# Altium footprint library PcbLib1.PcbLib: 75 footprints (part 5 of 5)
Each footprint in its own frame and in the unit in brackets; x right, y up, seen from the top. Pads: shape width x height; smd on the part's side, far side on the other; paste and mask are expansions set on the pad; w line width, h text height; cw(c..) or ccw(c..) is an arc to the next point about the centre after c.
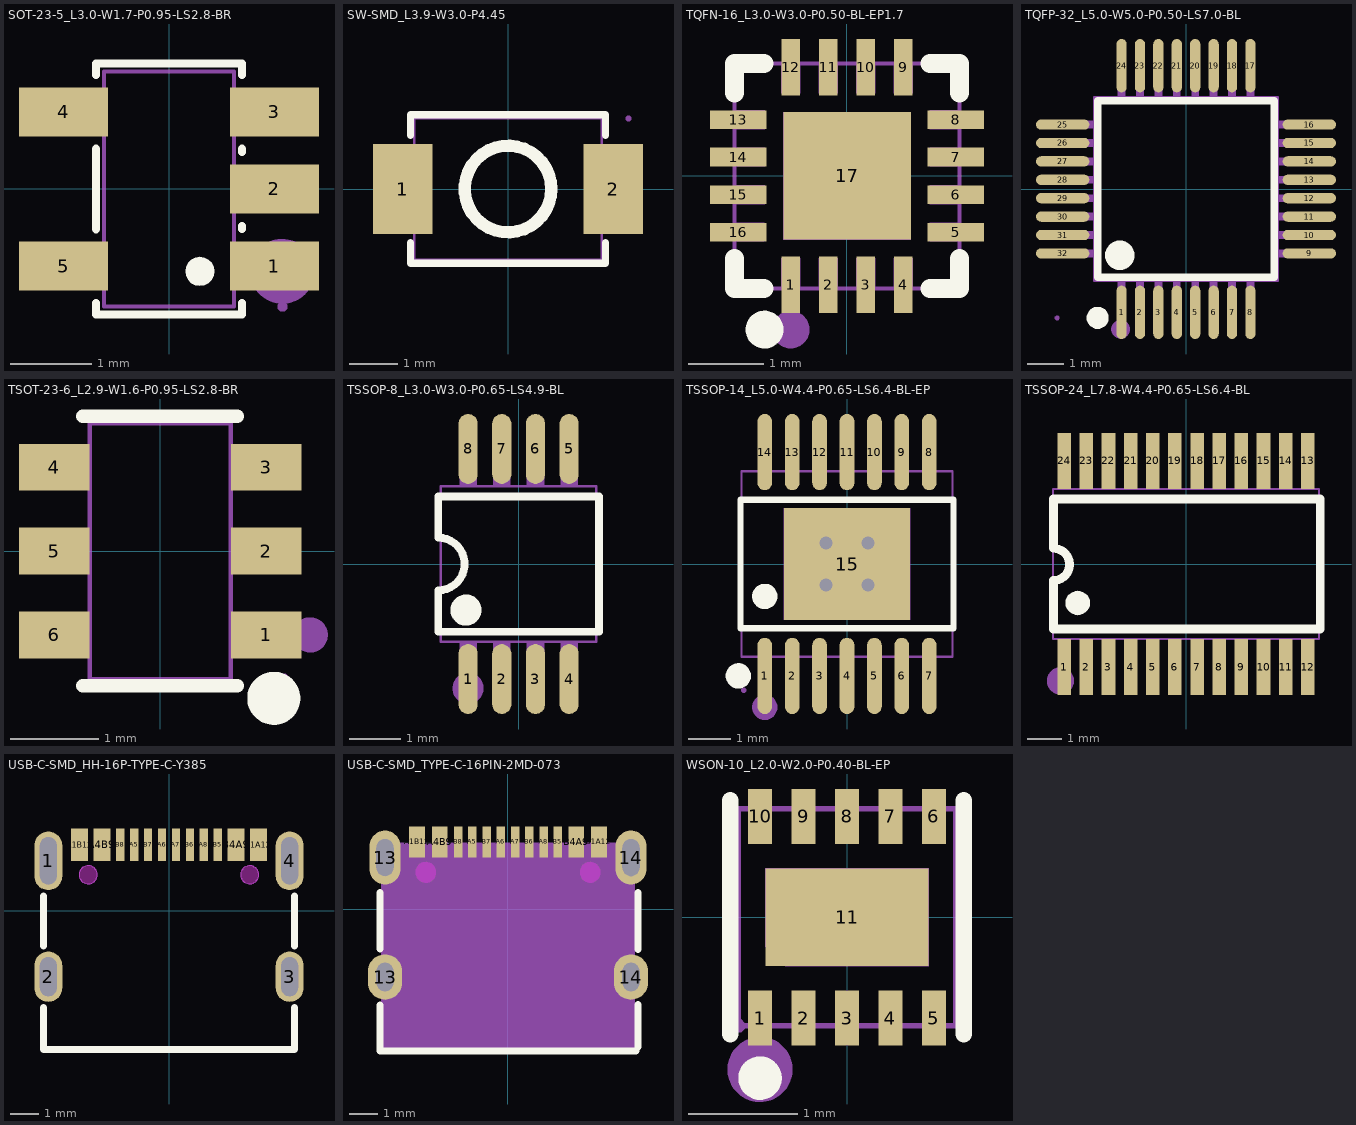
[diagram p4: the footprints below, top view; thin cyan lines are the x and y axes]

## SOT-23-5_L3.0-W1.7-P0.95-LS2.8-BR [mm]
pads (5):
  rect 1.1x0.6 smd: 1(1.3,-0.95) 2(1.3,0) 3(1.3,0.95) 4(-1.3,0.95) 5(-1.3,-0.95)
Top Overlay:
  region: 0.204,-1.016 0.212,-0.961 0.237,-0.911 0.276,-0.871 0.326,-0.846 0.381,-0.837 0.436,-0.846 0.486,-0.871 0.525,-0.911 0.55,-0.961 0.558,-1.016 0.55,-1.071 0.525,-1.121 0.486,-1.161 0.436,-1.186 0.381,-1.195 0.326,-1.186 0.276,-1.161 0.237,-1.121 0.212,-1.071 0.204,-1.016
  lines w0.1: -0.9,-1.404 -0.9,-1.55 0.9,-1.55 0.9,-1.404 ; -0.9,-0.496 -0.9,0.496 ; -0.9,1.404 -0.9,1.55 0.9,1.55 0.9,1.404 ; 0.9,-0.496 0.9,-0.454 ; 0.9,0.454 0.9,0.496
Mechanical 2:
  circle w0.4: c1.397,-1.016 r0.2
Mechanical 6:
  lines w0.051: -0.8,-1.45 -0.8,1.45 0.8,1.45 0.8,-1.45 -0.8,-1.45
Mechanical 7:
  region: -0.96,-1.15 -0.96,-0.75 -0.79,-0.75 -0.79,-1.15
  region: -0.96,0.75 -0.96,1.15 -0.79,1.15 -0.79,0.75
  region: 0.79,0.75 0.79,1.15 0.96,1.15 0.96,0.75
  region: 0.79,-0.2 0.79,0.2 0.96,0.2 0.96,-0.2
  region: 0.79,-1.15 0.79,-0.75 0.96,-0.75 0.96,-1.15
Mechanical 8:
  region: 1.46,-1.45 1.46,-1.475 1.425,-1.51 1.375,-1.51 1.34,-1.475 1.34,-1.45 1.34,-1.425 1.375,-1.39 1.425,-1.39 1.46,-1.425 1.46,-1.45
Mechanical 9:
  region: -1.4,-1.15 -1.4,-0.75 -0.95,-0.75 -0.95,-1.15
  region: -1.4,0.75 -1.4,1.15 -0.95,1.15 -0.95,0.75
  region: 0.95,0.75 0.95,1.15 1.4,1.15 1.4,0.75
  region: 0.95,-0.2 0.95,0.2 1.4,0.2 1.4,-0.2
  region: 0.95,-1.15 0.95,-0.75 1.4,-0.75 1.4,-1.15

## SW-SMD_L3.9-W3.0-P4.45 [mm]
pads (2):
  rect 1.23x1.86 smd: 1(-2.185,0) 2(2.185,0)
Top Overlay:
  circle w0.254: c0,0 r0.9
  lines w0.152: -2.026,-1.11 -2.026,-1.541 2.026,-1.541 2.026,-1.11 ; -2.026,1.11 -2.026,1.541 2.026,1.541 2.026,1.11
Mechanical 6:
  lines w0.051: -1.95,-1.465 -1.95,1.465 1.95,1.465 1.95,-1.465 -1.95,-1.465
Mechanical 8:
  region: 2.56,1.465 2.56,1.44 2.525,1.405 2.475,1.405 2.44,1.44 2.44,1.465 2.44,1.49 2.475,1.525 2.525,1.525 2.56,1.49 2.56,1.465
Mechanical 9:
  region: -2.5,0.65 -2.5,-0.65 -1.6,-0.65 -1.6,0.65
  region: 2.5,0.65 2.5,-0.65 1.6,-0.65 1.6,0.65

## TQFN-16_L3.0-W3.0-P0.50-BL-EP1.7 [mm]
pads (17):
  rect 0.25x0.75 smd paste-100 mask+0.051: 1(-0.748,-1.45) 2(-0.249,-1.45) 3(0.252,-1.45) 4(0.751,-1.45) 9(0.75,1.45) 10(0.25,1.45) 11(-0.25,1.45) 12(-0.749,1.45)
  rect 0.75x0.25 smd paste-100 mask+0.051: 5(1.45,-0.75) 6(1.45,-0.25) 7(1.45,0.25) 8(1.45,0.75) 13(-1.45,0.75) 14(-1.45,0.25) 15(-1.45,-0.25) 16(-1.45,-0.75)
  rect 1.7x1.7 smd paste-100 mask+0.051: 17(0,0)
Top Overlay:
  circle w0.254: c-1.1,-2.05 r0.125
  lines w0.254: -1.5,-1.104 -1.5,-1.5 -1.105,-1.5 ; -1.5,1.108 -1.5,1.5 -1.105,1.5 ; 1.106,1.5 1.5,1.5 1.5,1.108 ; 1.108,-1.5 1.5,-1.5 1.5,-1.104
Top Paste:
  region: 0.876,-1.075 0.626,-1.075 0.626,-1.825 0.876,-1.825
  region: 0.377,-1.075 0.127,-1.075 0.127,-1.825 0.377,-1.825
  region: -0.124,-1.075 -0.374,-1.075 -0.374,-1.825 -0.124,-1.825
  region: -0.623,-1.075 -0.873,-1.075 -0.873,-1.825 -0.623,-1.825
  region: 0.876,1.825 0.626,1.825 0.626,1.075 0.876,1.075
  region: 0.376,1.825 0.126,1.825 0.126,1.075 0.376,1.075
  region: -0.124,1.825 -0.374,1.825 -0.374,1.075 -0.124,1.075
  region: -0.624,1.825 -0.874,1.825 -0.874,1.075 -0.624,1.075
  region: 1.825,-0.875 1.825,-0.625 1.075,-0.625 1.075,-0.875
  region: 1.825,-0.375 1.825,-0.125 1.075,-0.125 1.075,-0.375
  region: 1.825,0.125 1.825,0.375 1.075,0.375 1.075,0.125
  region: 1.825,0.625 1.825,0.875 1.075,0.875 1.075,0.625
  region: -1.075,-0.875 -1.075,-0.625 -1.825,-0.625 -1.825,-0.875
  region: -1.075,-0.375 -1.075,-0.125 -1.825,-0.125 -1.825,-0.375
  region: -1.075,0.125 -1.075,0.375 -1.825,0.375 -1.825,0.125
  region: -1.075,0.625 -1.075,0.875 -1.825,0.875 -1.825,0.625
  region: -0.68,0.68 0.68,0.68 0.68,-0.68 -0.68,-0.68
Mechanical 2:
  circle w0.25: c-0.75,-2.05 r0.125
Mechanical 6:
  lines w0.051: -1.5,-1.5 -1.5,1.5 1.5,1.5 1.5,-1.5 -1.5,-1.5
Mechanical 8:
  region: -1.44,-1.5 -1.44,-1.525 -1.475,-1.56 -1.525,-1.56 -1.56,-1.525 -1.56,-1.5 -1.56,-1.475 -1.525,-1.44 -1.475,-1.44 -1.44,-1.475 -1.44,-1.5
Mechanical 9:
  region: -0.85,0.85 0.85,0.85 0.85,-0.85 -0.85,-0.85
  region: -0.623,-1.5 -0.873,-1.5 -0.873,-1.1 -0.623,-1.1
  region: -0.124,-1.5 -0.374,-1.5 -0.374,-1.1 -0.124,-1.1
  region: 0.377,-1.5 0.127,-1.5 0.127,-1.1 0.377,-1.1
  region: 0.876,-1.5 0.626,-1.5 0.626,-1.1 0.876,-1.1
  region: 1.1,-0.875 1.1,-0.625 1.5,-0.625 1.5,-0.875
  region: 1.1,-0.375 1.1,-0.125 1.5,-0.125 1.5,-0.375
  region: 1.1,0.125 1.1,0.375 1.5,0.375 1.5,0.125
  region: 1.1,0.625 1.1,0.875 1.5,0.875 1.5,0.625
  region: 0.625,1.5 0.875,1.5 0.875,1.1 0.625,1.1
  region: 0.125,1.5 0.375,1.5 0.375,1.1 0.125,1.1
  region: -0.374,1.5 -0.124,1.5 -0.124,1.1 -0.374,1.1
  region: -0.874,1.5 -0.624,1.5 -0.624,1.1 -0.874,1.1
  region: -1.1,0.875 -1.1,0.625 -1.5,0.625 -1.5,0.875
  region: -1.1,0.375 -1.1,0.125 -1.5,0.125 -1.5,0.375
  region: -1.1,-0.125 -1.1,-0.375 -1.5,-0.375 -1.5,-0.125
  region: -1.1,-0.625 -1.1,-0.875 -1.5,-0.875 -1.5,-0.625

## TQFP-32_L5.0-W5.0-P0.50-LS7.0-BL [mm]
pads (32):
  oval 0.28x1.45 smd: 1(-1.75,-3.35) 2(-1.25,-3.35) 3(-0.75,-3.35) 4(-0.25,-3.35) 5(0.25,-3.35) 6(0.75,-3.35) 7(1.25,-3.35) 8(1.75,-3.35) 17(1.75,3.35) 18(1.25,3.35) 19(0.75,3.35) 20(0.25,3.35) 21(-0.25,3.35) 22(-0.75,3.35) 23(-1.25,3.35) 24(-1.75,3.35)
  oval 1.45x0.28 smd: 9(3.35,-1.75) 10(3.35,-1.25) 11(3.35,-0.75) 12(3.35,-0.25) 13(3.35,0.25) 14(3.35,0.75) 15(3.35,1.25) 16(3.35,1.75) 25(-3.35,1.75) 26(-3.35,1.25) 27(-3.35,0.75) 28(-3.35,0.25) 29(-3.35,-0.25) 30(-3.35,-0.75) 31(-3.35,-1.25) 32(-3.35,-1.75)
Top Overlay:
  lines w0.2: -2.4,-2.4 -2.4,2.4 2.4,2.4 2.4,-2.4 -2.4,-2.4
  lines w0.3: -2.4,-3.35 ccw(c-2.399,-3.5) -2.398,-3.35
  lines w0.4: -1.801,-1.6 ccw(c-1.798,-1.8) -1.796,-1.6
Mechanical 2:
  circle w0.254: c-1.778,-3.81 r0.127
Mechanical 6:
  lines w0.051: -2.5,-2.5 -2.5,2.5 2.5,2.5 2.5,-2.5 -2.5,-2.5
Mechanical 7:
  drawing of 32 lines, arcs and shapes, not listed
Mechanical 8:
  region: -3.44,-3.5 -3.44,-3.525 -3.475,-3.56 -3.525,-3.56 -3.56,-3.525 -3.56,-3.5 -3.56,-3.475 -3.525,-3.44 -3.475,-3.44 -3.44,-3.475 -3.44,-3.5
Mechanical 9:
  drawing of 32 lines, arcs and shapes, not listed

## TSOT-23-6_L2.9-W1.6-P0.95-LS2.8-BR [mm]
pads (6):
  rect 0.8x0.532 smd: 1(1.2,-0.95) 2(1.2,0) 3(1.2,0.95) 4(-1.2,0.95) 5(-1.2,0) 6(-1.2,-0.95)
Top Overlay:
  circle w0.3: c1.287,-1.669 r0.15
  lines w0.152: -0.876,-1.526 0.876,-1.526 ; -0.876,1.526 0.876,1.526
Mechanical 2:
  circle w0.2: c1.7,-0.95 r0.1
Mechanical 6:
  lines w0.051: -0.8,-1.45 0.8,-1.45 0.8,1.45 -0.8,1.45 -0.8,-1.45
Mechanical 7:
  region: -0.96,-1.15 -0.96,-0.75 -0.79,-0.75 -0.79,-1.15
  region: -0.96,-0.2 -0.96,0.2 -0.79,0.2 -0.79,-0.2
  region: -0.96,0.75 -0.96,1.15 -0.79,1.15 -0.79,0.75
  region: 0.79,0.75 0.79,1.15 0.96,1.15 0.96,0.75
  region: 0.79,-0.2 0.79,0.2 0.96,0.2 0.96,-0.2
  region: 0.79,-1.15 0.79,-0.75 0.96,-0.75 0.96,-1.15
Mechanical 8:
  region: 1.46,-1.45 1.46,-1.475 1.425,-1.51 1.375,-1.51 1.34,-1.475 1.34,-1.45 1.34,-1.425 1.375,-1.39 1.425,-1.39 1.46,-1.425 1.46,-1.45
Mechanical 9:
  region: -0.95,-1.15 -0.95,-0.75 -1.4,-0.75 -1.4,-1.15
  region: -0.95,-0.2 -0.95,0.2 -1.4,0.2 -1.4,-0.2
  region: -0.95,0.75 -0.95,1.15 -1.4,1.15 -1.4,0.75
  region: 0.95,0.75 0.95,1.15 1.4,1.15 1.4,0.75
  region: 0.95,-0.2 0.95,0.2 1.4,0.2 1.4,-0.2
  region: 0.95,-1.15 0.95,-0.75 1.4,-0.75 1.4,-1.15

## TSSOP-8_L3.0-W3.0-P0.65-LS4.9-BL [mm]
pads (8):
  oval 0.37x1.35 smd: 1(-0.975,-2.22) 2(-0.325,-2.22) 3(0.325,-2.22) 4(0.975,-2.22) 5(0.975,2.22) 6(0.325,2.22) 7(-0.325,2.22) 8(-0.975,2.22)
Top Overlay:
  circle w0.3: c-1.016,-0.889 r0.15
  lines w0.152: 1.552,1.298 1.552,-1.308 -1.552,-1.308 -1.552,-0.508 ccw(c-1.552,0) -1.552,0.508 -1.552,1.302 1.552,1.302
Mechanical 2:
  circle w0.3: c-0.975,-2.4 r0.15
Mechanical 6:
  lines w0.051: -1.5,-1.5 -1.5,1.5 1.5,1.5 1.5,-1.5 -1.5,-1.5
Mechanical 7:
  region: 0.16,1.49 0.16,1.91 0.49,1.91 0.49,1.49
  region: -0.49,1.49 -0.49,1.91 -0.16,1.91 -0.16,1.49
  region: -1.14,1.49 -1.14,1.91 -0.81,1.91 -0.81,1.49
  region: 0.16,-1.91 0.16,-1.49 0.49,-1.49 0.49,-1.91
  region: -0.49,-1.91 -0.49,-1.49 -0.16,-1.49 -0.16,-1.91
  region: -1.14,-1.91 -1.14,-1.49 -0.81,-1.49 -0.81,-1.91
  region: 0.81,1.49 0.81,1.91 1.14,1.91 1.14,1.49
  region: 0.81,-1.91 0.81,-1.49 1.14,-1.49 1.14,-1.91
Mechanical 8:
  region: -0.956,-0.889 -0.956,-0.914 -0.991,-0.949 -1.041,-0.949 -1.076,-0.914 -1.076,-0.889 -1.076,-0.864 -1.041,-0.829 -0.991,-0.829 -0.956,-0.864 -0.956,-0.889
Mechanical 9:
  region: 0.16,1.9 0.16,2.45 0.49,2.45 0.49,1.9
  region: -0.49,1.9 -0.49,2.45 -0.16,2.45 -0.16,1.9
  region: -1.14,1.9 -1.14,2.45 -0.81,2.45 -0.81,1.9
  region: 0.16,-2.45 0.16,-1.9 0.49,-1.9 0.49,-2.45
  region: -0.49,-2.45 -0.49,-1.9 -0.16,-1.9 -0.16,-2.45
  region: -1.14,-2.45 -1.14,-1.9 -0.81,-1.9 -0.81,-2.45
  region: 0.81,1.9 0.81,2.45 1.14,2.45 1.14,1.9
  region: 0.81,-2.45 0.81,-1.9 1.14,-1.9 1.14,-2.45

## TSSOP-14_L5.0-W4.4-P0.65-LS6.4-BL-EP [mm]
pads (15):
  oval 0.35x1.809 smd: 1(-1.95,-2.655) 2(-1.3,-2.655) 3(-0.65,-2.655) 4(0,-2.655) 5(0.65,-2.655) 6(1.3,-2.655) 7(1.95,-2.655) 8(1.95,2.655) 9(1.3,2.655) 10(0.65,2.655) 11(0,2.655) 12(-0.65,2.655) 13(-1.3,2.655) 14(-1.95,2.655)
  rect 3x2.65 smd: 15(0,0)
via 0.495,-0.495 diameter 0.61 hole 0.305
via -0.495,-0.495 diameter 0.61 hole 0.305
via -0.495,0.495 diameter 0.61 hole 0.305
via 0.495,0.495 diameter 0.61 hole 0.305
Top Overlay:
  circle w0.3: c-2.577,-2.655 r0.15
  circle w0.3: c-1.95,-0.769 r0.15
  lines w0.152: -2.526,-1.521 2.526,-1.521 2.526,1.521 -2.526,1.521 -2.526,-1.521
Mechanical 2:
  circle w0.3: c-1.95,-3.4 r0.15
Mechanical 6:
  lines w0.051: -2.5,-2.2 2.5,-2.2 2.5,2.2 -2.5,2.2 -2.5,-2.2
Mechanical 7:
  region: 1.825,2.37 1.825,1.94 2.075,1.94 2.075,2.37
  region: 1.175,2.37 1.175,1.94 1.425,1.94 1.425,2.37
  region: 0.525,2.37 0.525,1.94 0.775,1.94 0.775,2.37
  region: -0.125,2.37 -0.125,1.94 0.125,1.94 0.125,2.37
  region: -0.775,2.37 -0.775,1.94 -0.525,1.94 -0.525,2.37
  region: -1.425,2.37 -1.425,1.94 -1.175,1.94 -1.175,2.37
  region: -2.075,2.37 -2.075,1.94 -1.825,1.94 -1.825,2.37
  region: 1.825,-2.37 1.825,-1.94 2.075,-1.94 2.075,-2.37
  region: 1.175,-2.37 1.175,-1.94 1.425,-1.94 1.425,-2.37
  region: 0.525,-2.37 0.525,-1.94 0.775,-1.94 0.775,-2.37
  region: -0.125,-2.37 -0.125,-1.94 0.125,-1.94 0.125,-2.37
  region: -0.775,-2.37 -0.775,-1.94 -0.525,-1.94 -0.525,-2.37
  region: -1.425,-2.37 -1.425,-1.94 -1.175,-1.94 -1.175,-2.37
  region: -2.075,-2.37 -2.075,-1.94 -1.825,-1.94 -1.825,-2.37
Mechanical 8:
  region: -2.39,-3 -2.39,-3.025 -2.425,-3.06 -2.475,-3.06 -2.51,-3.025 -2.51,-3 -2.51,-2.975 -2.475,-2.94 -2.425,-2.94 -2.39,-2.975 -2.39,-3
Mechanical 9:
  region: -1.5,-1.325 -1.5,1.325 1.5,1.325 1.5,-1.325
  region: 1.825,3 1.825,2.36 2.075,2.36 2.075,3
  region: 1.175,3 1.175,2.36 1.425,2.36 1.425,3
  region: 0.525,3 0.525,2.36 0.775,2.36 0.775,3
  region: -0.125,3 -0.125,2.36 0.125,2.36 0.125,3
  region: -0.775,3 -0.775,2.36 -0.525,2.36 -0.525,3
  region: -1.425,3 -1.425,2.36 -1.175,2.36 -1.175,3
  region: -2.075,3 -2.075,2.36 -1.825,2.36 -1.825,3
  region: 1.825,-3 1.825,-2.36 2.075,-2.36 2.075,-3
  region: 1.175,-3 1.175,-2.36 1.425,-2.36 1.425,-3
  region: 0.525,-3 0.525,-2.36 0.775,-2.36 0.775,-3
  region: -0.125,-3 -0.125,-2.36 0.125,-2.36 0.125,-3
  region: -0.775,-3 -0.775,-2.36 -0.525,-2.36 -0.525,-3
  region: -1.425,-3 -1.425,-2.36 -1.175,-2.36 -1.175,-3
  region: -2.075,-3 -2.075,-2.36 -1.825,-2.36 -1.825,-3

## TSSOP-24_L7.8-W4.4-P0.65-LS6.4-BL [mm]
pads (24):
  rect 0.4x1.65 smd: 1(-3.575,-3.023) 2(-2.925,-3.023) 3(-2.275,-3.023) 4(-1.625,-3.023) 5(-0.975,-3.023) 6(-0.325,-3.023) 7(0.325,-3.023) 8(0.975,-3.023) 9(1.625,-3.023) 10(2.275,-3.023) 11(2.925,-3.023) 12(3.575,-3.023) 13(3.575,3.023) 14(2.925,3.023) 15(2.275,3.023) 16(1.625,3.023) 17(0.975,3.023) 18(0.325,3.023) 19(-0.325,3.023) 20(-0.975,3.023) 21(-1.625,3.023) 22(-2.275,3.023) 23(-2.925,3.023) 24(-3.575,3.023)
Top Overlay:
  region: -3.529,-1.143 -3.52,-1.064 -3.494,-0.989 -3.452,-0.922 -3.396,-0.866 -3.329,-0.824 -3.254,-0.798 -3.175,-0.789 -3.096,-0.798 -3.021,-0.824 -2.954,-0.866 -2.898,-0.922 -2.856,-0.989 -2.83,-1.064 -2.821,-1.143 -2.83,-1.222 -2.856,-1.297 -2.898,-1.364 -2.954,-1.42 -3.021,-1.462 -3.096,-1.488 -3.175,-1.497 -3.254,-1.488 -3.329,-1.462 -3.396,-1.42 -3.452,-1.364 -3.494,-1.297 -3.52,-1.222
  lines w0.254: -3.886,0.457 cw(c-3.886,-0.013) -3.886,-0.483 -3.886,-1.753 -3.886,-1.905 3.937,-1.905 3.937,1.905 -3.886,1.905 -3.886,1.753 -3.886,0.483
Mechanical 2:
  circle w0.4: c-3.683,-3.429 r0.2
Mechanical 6:
  lines w0.051: -3.9,-2.2 -3.9,2.2 3.9,2.2 3.9,-2.2 -3.9,-2.2
Mechanical 7:
  region: -0.225,2.588 -0.425,2.588 -0.425,2.188 -0.225,2.188
  region: -0.875,2.588 -1.075,2.588 -1.075,2.188 -0.875,2.188
  region: -1.525,2.588 -1.725,2.588 -1.725,2.188 -1.525,2.188
  region: -2.175,2.588 -2.375,2.588 -2.375,2.188 -2.175,2.188
  region: -2.825,2.588 -3.025,2.588 -3.025,2.188 -2.825,2.188
  region: -3.475,2.588 -3.675,2.588 -3.675,2.188 -3.475,2.188
  region: 3.675,2.588 3.475,2.588 3.475,2.188 3.675,2.188
  region: 3.025,2.588 2.825,2.588 2.825,2.188 3.025,2.188
  region: 2.375,2.588 2.175,2.588 2.175,2.188 2.375,2.188
  region: 1.725,2.588 1.525,2.588 1.525,2.188 1.725,2.188
  region: 1.075,2.588 0.875,2.588 0.875,2.188 1.075,2.188
  region: 0.425,2.588 0.225,2.588 0.225,2.188 0.425,2.188
  region: 0.225,-2.588 0.425,-2.588 0.425,-2.188 0.225,-2.188
  region: 0.875,-2.588 1.075,-2.588 1.075,-2.188 0.875,-2.188
  region: 1.525,-2.588 1.725,-2.588 1.725,-2.188 1.525,-2.188
  region: 2.175,-2.588 2.375,-2.588 2.375,-2.188 2.175,-2.188
  region: 2.825,-2.588 3.025,-2.588 3.025,-2.188 2.825,-2.188
  region: 3.475,-2.588 3.675,-2.588 3.675,-2.188 3.475,-2.188
  region: -3.675,-2.588 -3.475,-2.588 -3.475,-2.188 -3.675,-2.188
  region: -3.025,-2.588 -2.825,-2.588 -2.825,-2.188 -3.025,-2.188
  region: -2.375,-2.588 -2.175,-2.588 -2.175,-2.188 -2.375,-2.188
  region: -1.725,-2.588 -1.525,-2.588 -1.525,-2.188 -1.725,-2.188
  region: -1.075,-2.588 -0.875,-2.588 -0.875,-2.188 -1.075,-2.188
  region: -0.425,-2.588 -0.225,-2.588 -0.225,-2.188 -0.425,-2.188
Mechanical 8:
  region: -3.84,-3.186 -3.84,-3.211 -3.875,-3.246 -3.925,-3.246 -3.96,-3.211 -3.96,-3.186 -3.96,-3.161 -3.925,-3.126 -3.875,-3.126 -3.84,-3.161 -3.84,-3.186
Mechanical 9:
  region: -0.225,2.586 -0.425,2.586 -0.425,3.186 -0.225,3.186
  region: -0.875,2.586 -1.075,2.586 -1.075,3.186 -0.875,3.186
  region: -1.525,2.586 -1.725,2.586 -1.725,3.186 -1.525,3.186
  region: -2.175,2.586 -2.375,2.586 -2.375,3.186 -2.175,3.186
  region: -2.825,2.586 -3.025,2.586 -3.025,3.186 -2.825,3.186
  region: -3.475,2.586 -3.675,2.586 -3.675,3.186 -3.475,3.186
  region: 3.675,2.586 3.475,2.586 3.475,3.186 3.675,3.186
  region: 3.025,2.586 2.825,2.586 2.825,3.186 3.025,3.186
  region: 2.375,2.586 2.175,2.586 2.175,3.186 2.375,3.186
  region: 1.725,2.586 1.525,2.586 1.525,3.186 1.725,3.186
  region: 1.075,2.586 0.875,2.586 0.875,3.186 1.075,3.186
  region: 0.425,2.586 0.225,2.586 0.225,3.186 0.425,3.186
  region: 0.225,-2.586 0.425,-2.586 0.425,-3.186 0.225,-3.186
  region: 0.875,-2.586 1.075,-2.586 1.075,-3.186 0.875,-3.186
  region: 1.525,-2.586 1.725,-2.586 1.725,-3.186 1.525,-3.186
  region: 2.175,-2.586 2.375,-2.586 2.375,-3.186 2.175,-3.186
  region: 2.825,-2.586 3.025,-2.586 3.025,-3.186 2.825,-3.186
  region: 3.475,-2.586 3.675,-2.586 3.675,-3.186 3.475,-3.186
  region: -3.675,-2.586 -3.475,-2.586 -3.475,-3.186 -3.675,-3.186
  region: -3.025,-2.586 -2.825,-2.586 -2.825,-3.186 -3.025,-3.186
  region: -2.375,-2.586 -2.175,-2.586 -2.175,-3.186 -2.375,-3.186
  region: -1.725,-2.586 -1.525,-2.586 -1.525,-3.186 -1.725,-3.186
  region: -1.075,-2.586 -0.875,-2.586 -0.875,-3.186 -1.075,-3.186
  region: -0.425,-2.586 -0.225,-2.586 -0.225,-3.186 -0.425,-3.186

## USB-C-SMD_HH-16P-TYPE-C-Y385 [mm]
pads (16):
  oval 1x2.1 hole 0.6 slot 1.7 at 90 deg copper offset 0,0 paste-2539.97 mask+0.051: 1(-4.32,1.787) 4(4.32,1.787)
  oval 1x1.8 hole 0.6 slot 1.4 at 90 deg paste-2539.97 mask+0.051: 2(-4.32,-2.363) 3(4.32,-2.363)
  rect 0.6x1.15 smd paste+0 mask+0.05: A1B12(-3.2,2.363) A4B9(-2.4,2.363) B1A12(3.2,2.363) B4A9(2.4,2.363)
  rect 0.3x1.15 smd paste+0 mask+0.051: A5(-1.25,2.363) A6(-0.25,2.363) A7(0.25,2.363) A8(1.25,2.363) B5(1.75,2.363) B6(0.75,2.363) B7(-0.75,2.363) B8(-1.75,2.363)
Top Overlay:
  lines w0.254: -4.5,-3.471 -4.5,-4.962 4.5,-4.962 4.5,-3.471 ; -4.5,-1.254 -4.5,0.529 ; 4.5,-1.254 4.5,0.529
Keep-Out Layer:
  board cut-out: 3.215,1.287 3.215,1.223 3.166,1.103 3.074,1.012 2.955,0.962 2.825,0.962 2.706,1.012 2.615,1.103 2.565,1.223 2.565,1.287 2.565,1.352 2.615,1.471 2.706,1.563 2.825,1.612 2.955,1.612 3.074,1.563 3.166,1.471 3.215,1.352 3.215,1.287
  board cut-out: -2.565,1.287 -2.565,1.223 -2.614,1.103 -2.706,1.012 -2.825,0.962 -2.955,0.962 -3.074,1.012 -3.166,1.103 -3.215,1.223 -3.215,1.287 -3.215,1.352 -3.166,1.471 -3.074,1.563 -2.955,1.612 -2.825,1.612 -2.706,1.563 -2.614,1.471 -2.565,1.352 -2.565,1.287
Keep-Out Layer:
  circle w0.003: c2.89,1.287 r0.325
  circle w0.003: c-2.89,1.287 r0.325
  region: 3.215,1.287 3.206,1.21 3.178,1.136 3.133,1.072 3.075,1.02 3.005,0.984 2.929,0.965 2.851,0.965 2.775,0.984 2.705,1.02 2.647,1.072 2.602,1.136 2.574,1.21 2.565,1.287 2.574,1.365 2.602,1.438 2.647,1.503 2.705,1.555 2.775,1.591 2.851,1.61 2.929,1.61 3.005,1.591 3.075,1.555 3.133,1.503 3.178,1.438 3.206,1.365
  region: 3.215,1.287 3.215,1.223 3.166,1.103 3.074,1.012 2.955,0.962 2.825,0.962 2.706,1.012 2.615,1.103 2.565,1.223 2.565,1.287 2.565,1.352 2.615,1.471 2.706,1.563 2.825,1.612 2.955,1.612 3.074,1.563 3.166,1.471 3.215,1.352 3.215,1.287
  region: -2.565,1.287 -2.574,1.21 -2.602,1.136 -2.647,1.072 -2.705,1.02 -2.775,0.984 -2.851,0.965 -2.929,0.965 -3.005,0.984 -3.075,1.02 -3.133,1.072 -3.178,1.136 -3.206,1.21 -3.215,1.287 -3.206,1.365 -3.178,1.438 -3.133,1.503 -3.075,1.555 -3.005,1.591 -2.929,1.61 -2.851,1.61 -2.775,1.591 -2.705,1.555 -2.647,1.503 -2.602,1.438 -2.574,1.365
  region: -2.565,1.287 -2.565,1.223 -2.614,1.103 -2.706,1.012 -2.825,0.962 -2.955,0.962 -3.074,1.012 -3.166,1.103 -3.215,1.223 -3.215,1.287 -3.215,1.352 -3.166,1.471 -3.074,1.563 -2.955,1.612 -2.825,1.612 -2.706,1.563 -2.614,1.471 -2.565,1.352 -2.565,1.287
Mechanical 1:
  circle w0.003: c2.89,1.287 r0.325
  circle w0.003: c-2.89,1.287 r0.325
Mechanical 11:
  region: -4.44,2.265 -4.44,2.252 -4.458,2.235 -4.483,2.235 -4.5,2.252 -4.5,2.265 -4.5,2.277 -4.483,2.295 -4.458,2.295 -4.44,2.277 -4.44,2.265

## USB-C-SMD_TYPE-C-16PIN-2MD-073 [mm]
pads (16):
  oval 1.2x1.6 hole 0.6 slot 1 at 90 deg paste-2539.97 mask+0.05: 13(-4.325,-2.375) 14(4.325,-2.375)
  oval 1.1x1.9 hole 0.6 slot 1.3 at 90 deg paste-2539.97 mask+0.05: 13(-4.325,1.825) 14(4.325,1.825)
  rect 0.55x1.1 smd paste+0 mask+0.05: A1B12(-3.2,2.375) A4B9(-2.4,2.375) B1A12(3.2,2.375) B4A9(2.4,2.375)
  rect 0.3x1.1 smd paste+0 mask+0.05: A5(-1.25,2.375) A6(-0.25,2.375) A7(0.25,2.375) A8(1.25,2.375) B5(1.75,2.375) B6(0.75,2.375) B7(-0.75,2.375) B8(-1.75,2.375)
Top Overlay:
  lines w0.254: -4.5,-3.356 -4.5,-4.975 4.5,-4.975 ; -4.5,-1.394 -4.5,0.594 ; 4.572,-4.826 4.572,-3.353 ; 4.572,-1.397 4.572,0.597
Keep-Out Layer:
  board cut-out: 3.24,1.305 3.24,1.235 3.187,1.107 3.088,1.008 2.96,0.955 2.821,0.955 2.692,1.008 2.593,1.107 2.54,1.235 2.54,1.305 2.54,1.375 2.593,1.503 2.692,1.602 2.821,1.655 2.96,1.655 3.088,1.602 3.187,1.503 3.24,1.375 3.24,1.305
  board cut-out: -2.54,1.305 -2.54,1.235 -2.593,1.107 -2.692,1.008 -2.82,0.955 -2.96,0.955 -3.088,1.008 -3.187,1.107 -3.24,1.235 -3.24,1.305 -3.24,1.375 -3.187,1.503 -3.088,1.602 -2.96,1.655 -2.82,1.655 -2.692,1.602 -2.593,1.503 -2.54,1.375 -2.54,1.305
Keep-Out Layer:
  circle w0.003: c2.89,1.305 r0.35
  circle w0.003: c-2.89,1.305 r0.35
  region: 3.24,1.305 3.231,1.227 3.205,1.153 3.164,1.087 3.108,1.031 3.042,0.99 2.968,0.964 2.89,0.955 2.812,0.964 2.738,0.99 2.672,1.031 2.616,1.087 2.575,1.153 2.549,1.227 2.54,1.305 2.549,1.383 2.575,1.457 2.616,1.523 2.672,1.579 2.738,1.62 2.812,1.646 2.89,1.655 2.968,1.646 3.042,1.62 3.108,1.579 3.164,1.523 3.205,1.457 3.231,1.383
  region: 3.24,1.305 3.24,1.235 3.187,1.107 3.088,1.008 2.96,0.955 2.821,0.955 2.692,1.008 2.593,1.107 2.54,1.235 2.54,1.305 2.54,1.375 2.593,1.503 2.692,1.602 2.821,1.655 2.96,1.655 3.088,1.602 3.187,1.503 3.24,1.375 3.24,1.305
  region: -2.54,1.305 -2.549,1.227 -2.575,1.153 -2.616,1.087 -2.672,1.031 -2.738,0.99 -2.812,0.964 -2.89,0.955 -2.968,0.964 -3.042,0.99 -3.108,1.031 -3.164,1.087 -3.205,1.153 -3.231,1.227 -3.24,1.305 -3.231,1.383 -3.205,1.457 -3.164,1.523 -3.108,1.579 -3.042,1.62 -2.968,1.646 -2.89,1.655 -2.812,1.646 -2.738,1.62 -2.672,1.579 -2.616,1.523 -2.575,1.457 -2.549,1.383
  region: -2.54,1.305 -2.54,1.235 -2.593,1.107 -2.692,1.008 -2.82,0.955 -2.96,0.955 -3.088,1.008 -3.187,1.107 -3.24,1.235 -3.24,1.305 -3.24,1.375 -3.187,1.503 -3.088,1.602 -2.96,1.655 -2.82,1.655 -2.692,1.602 -2.593,1.503 -2.54,1.375 -2.54,1.305
Mechanical 1:
  circle w0.003: c2.89,1.305 r0.35
  circle w0.003: c-2.89,1.305 r0.35
Mechanical 5:
  circle w0.25: c2.89,1.305 r0.125
  circle w0.25: c-2.89,1.305 r0.125
Mechanical 9:
  region: -4.45,-5.001 -4.45,2.349 4.45,2.349 4.45,-5.001
Mechanical 11:
  region: -4.42,2.649 -4.42,2.637 -4.438,2.619 -4.462,2.619 -4.48,2.637 -4.48,2.649 -4.48,2.662 -4.462,2.679 -4.438,2.679 -4.42,2.662 -4.42,2.649
Mechanical 12:
  region: -4.475,-1.975 -4.175,-1.975 -4.175,-2.775 -4.475,-2.775
  region: 4.175,-1.975 4.475,-1.975 4.475,-2.775 4.175,-2.775
  region: 4.175,2.375 4.475,2.375 4.475,1.275 4.175,1.275
  region: -4.45,2.349 -4.2,2.349 -4.2,1.249 -4.45,1.249
  region: 3,2.649 3.4,2.649 3.4,1.799 3,1.799
  region: 2.2,2.649 2.6,2.649 2.6,1.799 2.2,1.799
  region: -2.6,2.649 -2.2,2.649 -2.2,1.799 -2.6,1.799
  region: -3.4,2.649 -3,2.649 -3,1.799 -3.4,1.799
  region: 1.65,2.649 1.85,2.649 1.85,1.799 1.65,1.799
  region: 1.15,2.649 1.35,2.649 1.35,1.799 1.15,1.799
  region: 0.65,2.649 0.85,2.649 0.85,1.799 0.65,1.799
  region: 0.15,2.649 0.35,2.649 0.35,1.799 0.15,1.799
  region: -0.35,2.649 -0.15,2.649 -0.15,1.799 -0.35,1.799
  region: -1.35,2.649 -1.15,2.649 -1.15,1.799 -1.35,1.799
  region: -0.85,2.649 -0.65,2.649 -0.65,1.799 -0.85,1.799
  region: -1.85,2.649 -1.65,2.649 -1.65,1.799 -1.85,1.799

## WSON-10_L2.0-W2.0-P0.40-BL-EP [mm]
pads (11):
  rect 0.224x0.505 smd: 1(-0.8,-0.928) 2(-0.4,-0.928) 3(0,-0.928) 4(0.4,-0.928) 5(0.8,-0.928) 6(0.8,0.928) 7(0.4,0.928) 8(0,0.928) 9(-0.4,0.928) 10(-0.8,0.928)
  rect 1.5x0.9 smd: 11(0,0)
Top Overlay:
  circle w0.2: c-0.8,-1.48 r0.1
  lines w0.152: -1.076,-1.076 -1.076,1.076 ; 1.076,-1.076 1.076,1.076
Mechanical 2:
  circle w0.3: c-0.8,-1.4 r0.15
Mechanical 6:
  lines w0.051: -1,-1 -1,1 1,1 1,-1 -1,-1
Mechanical 8:
  region: -0.94,-1 -0.94,-1.025 -0.975,-1.06 -1.025,-1.06 -1.06,-1.025 -1.06,-1 -1.06,-0.975 -1.025,-0.94 -0.975,-0.94 -0.94,-0.975 -0.94,-1
Mechanical 9:
  region: -0.9,-1 -0.9,-0.7 -0.7,-0.7 -0.7,-1
  region: -0.5,-1 -0.5,-0.7 -0.3,-0.7 -0.3,-1
  region: -0.1,-1 -0.1,-0.7 0.1,-0.7 0.1,-1
  region: 0.3,-1 0.3,-0.7 0.5,-0.7 0.5,-1
  region: 0.7,-1 0.7,-0.7 0.9,-0.7 0.9,-1
  region: -0.9,1 -0.9,0.7 -0.7,0.7 -0.7,1
  region: -0.5,1 -0.5,0.7 -0.3,0.7 -0.3,1
  region: -0.1,1 -0.1,0.7 0.1,0.7 0.1,1
  region: 0.3,1 0.3,0.7 0.5,0.7 0.5,1
  region: 0.7,1 0.7,0.7 0.9,0.7 0.9,1
  region: -0.75,-0.27 -0.75,0.45 0.75,0.45 0.75,-0.45 -0.57,-0.45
